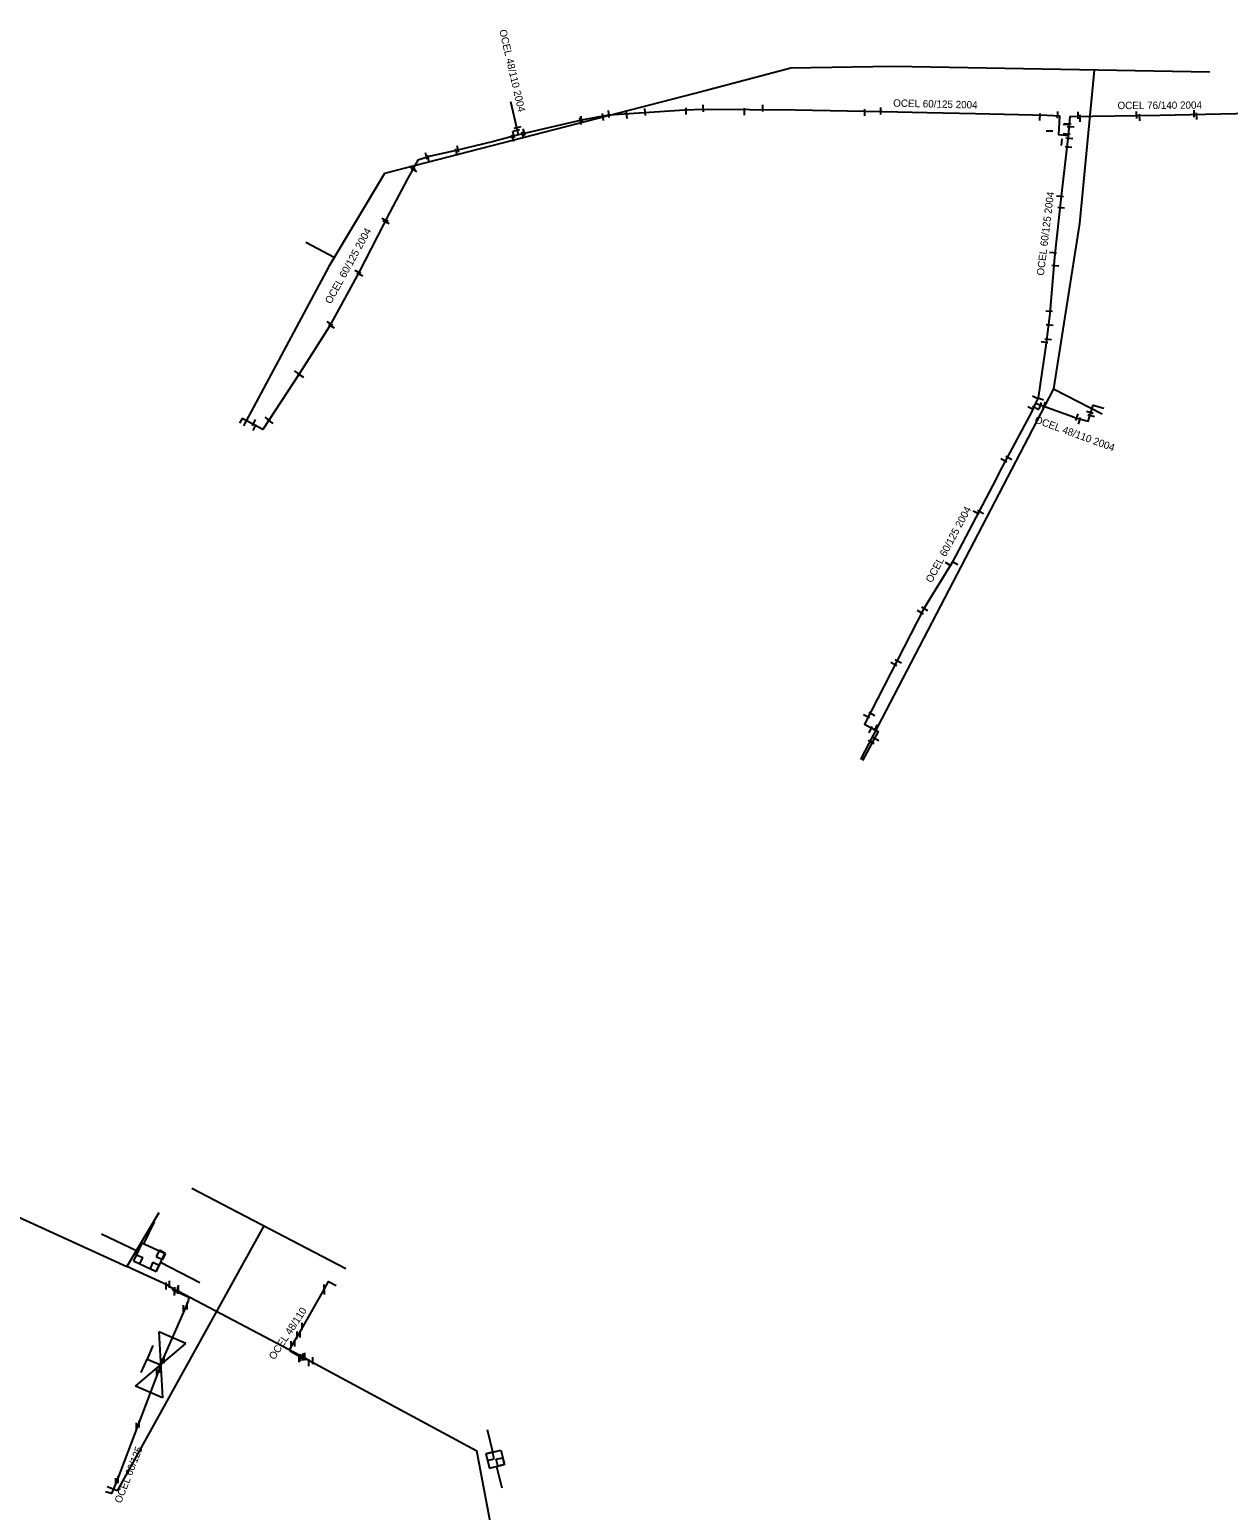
# Model space of a CAD drawing. Extents: x -642943 to -623314, y -1138561 to -1113539.
# Drawn here: x -642840.5 to -642718.5, y -1114329.8 to -1114179.2 of the extents above; entities that cross this region are included whole.
import ezdxf

# ---------------------------------------------------------------- set-up
doc = ezdxf.new("R2010")
doc.units = 0
for name, color, linetype in [('horkovod armatury', 7, 'Continuous'), ('horkovod dimenze', 7, 'Continuous'), ('horkovod předisol', 7, 'Continuous'), ('horkovod sváry', 7, 'Continuous'), ('horkovod trasa', 7, 'Continuous'), ('horkovod zrušený', 7, 'Continuous')]:
    doc.layers.add(name, color=color, linetype=linetype)

# ---------------------------------------------------------------- blocks, each defined once
blk = doc.blocks.new('POINT_DISPLAY')
blk.add_line((0, 0), (0, 0))
blk = doc.blocks.new('SPH')
at = {"layer": 'horkovod sváry'}
blk.add_line((0, -0.035), (0, 0.035), dxfattribs=at)
blk = doc.blocks.new('SCH_01_104')
at = {"layer": 'horkovod armatury'}
for p, q in [((10, 5), (-10, -5)), ((-10, -5), (-10, 5)), ((-10, 5), (10, -5)), ((-5, 5), (0, 5)), ((0, 5), (0, 0)), ((5, 5), (0, 5)), ((10, -5), (10, 5))]:
    blk.add_line(p, q, dxfattribs=at)

msp = doc.modelspace()

# ---------------------------------------------------------------- linework, layer by layer
at = {"layer": 'horkovod předisol'}
for p, q in [((-642790.76, -1114189.89), (-642791.55, -1114186.51)), ((-642827.34, -1114299.55), (-642830.61, -1114305.01)), ((-642812.3, -1114314.43), (-642825.98, -1114307.21)), ((-642812.3, -1114314.43), (-642795, -1114323.77)), ((-642788.02, -1114360.57), (-642795, -1114323.77))]:
    msp.add_line(p, q, dxfattribs=at)
for points in [[(-642734.85, -1114189.98), (-642735.8, -1114189.89), (-642735.7, -1114188), (-642736.98, -1114187.93), (-642744.26, -1114187.76), (-642749.19, -1114187.65), (-642753.72, -1114187.55), (-642762.62, -1114187.38), (-642771.87, -1114187.31), (-642773.86, -1114187.38), (-642781.54, -1114187.89), (-642781.97, -1114187.94), (-642784.36, -1114188.38), (-642790.76, -1114189.89)], [(-642714.7, -1114187.68), (-642725.5, -1114187.91), (-642734.68, -1114188.06), (-642734.85, -1114189.98)], [(-642790.76, -1114189.89), (-642793.31, -1114190.55), (-642797.1, -1114191.47), (-642799.72, -1114192.07), (-642800.99, -1114192.45), (-642802.06, -1114194.37), (-642803.84, -1114197.75), (-642806.99, -1114203.89), (-642810.02, -1114209.41), (-642813.03, -1114214.18), (-642816.75, -1114219.86), (-642818.86, -1114218.73), (-642819.14, -1114219.2)], [(-642734.85, -1114189.98), (-642735.54, -1114196.12), (-642736.24, -1114202.32), (-642736.7, -1114208.07), (-642737.11, -1114211.3), (-642737.91, -1114216.63), (-642738.15, -1114217.18)], [(-642738.15, -1114217.18), (-642738.54, -1114218.02), (-642741.79, -1114224.11), (-642742.17, -1114224.89), (-642746.65, -1114233.38), (-642749.56, -1114238.14), (-642755.55, -1114249.83), (-642754.16, -1114250.58), (-642755.76, -1114253.53)], [(-642738.15, -1114217.18), (-642734.41, -1114218.55), (-642733.99, -1114218.71), (-642732.82, -1114219), (-642732.31, -1114217.38), (-642731.21, -1114217.69)], [(-642877.13, -1114282.34), (-642874.67, -1114283.67), (-642863.97, -1114289.15), (-642853.5, -1114294.39), (-642852.54, -1114294.82), (-642851.65, -1114293.04), (-642849.52, -1114294.1), (-642850.35, -1114295.88), (-642849.53, -1114296.38), (-642830.61, -1114305.01)], [(-642825.98, -1114307.21), (-642826.45, -1114306.9), (-642830.61, -1114305.01)], [(-642812.3, -1114314.43), (-642812.45, -1114314.52), (-642813.96, -1114313.65), (-642813.99, -1114313.4), (-642813.7, -1114312.89), (-642812.96, -1114311.66), (-642810.51, -1114307.36), (-642810.07, -1114306.55), (-642809.29, -1114306.96)], [(-642825.98, -1114307.21), (-642825.91, -1114307.38), (-642824.29, -1114308.14), (-642824.35, -1114308.5), (-642824.64, -1114309.17), (-642826.96, -1114314.52), (-642827.42, -1114315.72), (-642829.49, -1114321.19), (-642831.62, -1114326.8), (-642832.14, -1114328.1), (-642832.78, -1114327.93)]]:
    msp.add_lwpolyline(points, dxfattribs=at)
at = {"layer": 'horkovod trasa'}
for p, q in [((-642790.76, -1114189.89), (-642791.55, -1114186.51)), ((-642827.34, -1114299.55), (-642830.61, -1114305.01)), ((-642812.3, -1114314.43), (-642825.98, -1114307.21)), ((-642812.3, -1114314.43), (-642795, -1114323.77)), ((-642788.02, -1114360.57), (-642795, -1114323.77))]:
    msp.add_line(p, q, dxfattribs=at)
for points in [[(-642734.85, -1114189.98), (-642735.8, -1114189.89), (-642735.7, -1114188), (-642736.98, -1114187.93), (-642744.26, -1114187.76), (-642749.19, -1114187.65), (-642753.72, -1114187.55), (-642762.62, -1114187.38), (-642771.87, -1114187.31), (-642773.86, -1114187.38), (-642781.54, -1114187.89), (-642781.97, -1114187.94), (-642784.36, -1114188.38), (-642790.76, -1114189.89)], [(-642714.7, -1114187.68), (-642725.5, -1114187.91), (-642734.68, -1114188.06), (-642734.85, -1114189.98)], [(-642790.76, -1114189.89), (-642793.31, -1114190.55), (-642797.1, -1114191.47), (-642799.72, -1114192.07), (-642800.99, -1114192.45), (-642802.06, -1114194.37), (-642803.84, -1114197.75), (-642806.99, -1114203.89), (-642810.02, -1114209.41), (-642813.03, -1114214.18), (-642816.75, -1114219.86), (-642818.86, -1114218.73), (-642819.14, -1114219.2)], [(-642734.85, -1114189.98), (-642735.54, -1114196.12), (-642736.24, -1114202.32), (-642736.7, -1114208.07), (-642737.11, -1114211.3), (-642737.91, -1114216.63), (-642738.15, -1114217.18)], [(-642738.15, -1114217.18), (-642738.54, -1114218.02), (-642741.79, -1114224.11), (-642742.17, -1114224.89), (-642746.65, -1114233.38), (-642749.56, -1114238.14), (-642755.55, -1114249.83), (-642754.16, -1114250.58), (-642755.76, -1114253.53)], [(-642738.15, -1114217.18), (-642734.41, -1114218.55), (-642733.99, -1114218.71), (-642732.82, -1114219), (-642732.31, -1114217.38), (-642731.21, -1114217.69)], [(-642877.13, -1114282.34), (-642874.67, -1114283.67), (-642863.97, -1114289.15), (-642853.5, -1114294.39), (-642852.54, -1114294.82), (-642851.65, -1114293.04), (-642849.52, -1114294.1), (-642850.35, -1114295.88), (-642849.53, -1114296.38), (-642830.61, -1114305.01)], [(-642825.98, -1114307.21), (-642826.45, -1114306.9), (-642830.61, -1114305.01)], [(-642812.3, -1114314.43), (-642812.45, -1114314.52), (-642813.96, -1114313.65), (-642813.99, -1114313.4), (-642813.7, -1114312.89), (-642812.96, -1114311.66), (-642810.51, -1114307.36), (-642810.07, -1114306.55), (-642809.29, -1114306.96)], [(-642825.98, -1114307.21), (-642825.91, -1114307.38), (-642824.29, -1114308.14), (-642824.35, -1114308.5), (-642824.64, -1114309.17), (-642826.96, -1114314.52), (-642827.42, -1114315.72), (-642829.49, -1114321.19), (-642831.62, -1114326.8), (-642832.14, -1114328.1), (-642832.78, -1114327.93)]]:
    msp.add_lwpolyline(points, dxfattribs=at)
at = {"layer": 'horkovod zrušený'}
for p, q in [((-642804.38, -1114193.8), (-642810.05, -1114203.28)), ((-642809.51, -1114202.37), (-642812.37, -1114200.83)), ((-642810.05, -1114203.28), (-642818.73, -1114219.5)), ((-642736.35, -1114215.71), (-642755.96, -1114253.43)), ((-642736.35, -1114215.71), (-642731.4, -1114218.27)), ((-642823.97, -1114297.05), (-642808.32, -1114305.22)), ((-642828.88, -1114302.72), (-642827.78, -1114300.47)), ((-642829.47, -1114303.5), (-642833.17, -1114301.71)), ((-642831.53, -1114327.84), (-642816.61, -1114300.89)), ((-642829.06, -1114302.63), (-642829.9, -1114304.45)), ((-642826.76, -1114303.7), (-642829.06, -1114302.63)), ((-642827.28, -1114303.36), (-642827.6, -1114303.98)), ((-642826.66, -1114303.68), (-642827.28, -1114303.36)), ((-642829.61, -1114303.81), (-642829.9, -1114304.45)), ((-642829.9, -1114304.45), (-642829.27, -1114304.74)), ((-642829.9, -1114304.45), (-642827.6, -1114305.51)), ((-642829.61, -1114303.81), (-642828.97, -1114304.11)), ((-642829.27, -1114304.74), (-642828.97, -1114304.11)), ((-642827.94, -1114304.58), (-642828.23, -1114305.22)), ((-642827.94, -1114304.58), (-642827.31, -1114304.88)), ((-642826.76, -1114303.7), (-642827.6, -1114305.51)), ((-642827.6, -1114303.98), (-642826.98, -1114304.3)), ((-642827.6, -1114305.51), (-642827.31, -1114304.88)), ((-642827.16, -1114304.57), (-642823.18, -1114306.65)), ((-642826.66, -1114303.68), (-642826.98, -1114304.3)), ((-642828.23, -1114305.22), (-642827.6, -1114305.51)), ((-642793.36, -1114323.88), (-642793.89, -1114321.64)), ((-642794.06, -1114324.06), (-642792.55, -1114323.68)), ((-642793.39, -1114323.89), (-642794.06, -1114324.06)), ((-642794.06, -1114324.06), (-642793.7, -1114325.51)), ((-642794.06, -1114324.06), (-642793.9, -1114324.74)), ((-642793.9, -1114324.74), (-642793.22, -1114324.57)), ((-642793.22, -1114324.57), (-642793.39, -1114323.89)), ((-642793.04, -1114324.62), (-642792.36, -1114324.46)), ((-642792.87, -1114325.3), (-642793.04, -1114324.62)), ((-642792.55, -1114323.68), (-642792.19, -1114325.14)), ((-642792.19, -1114325.13), (-642792.36, -1114324.46)), ((-642793.7, -1114325.51), (-642792.19, -1114325.14)), ((-642792.99, -1114325.34), (-642792.45, -1114327.52)), ((-642792.87, -1114325.3), (-642792.19, -1114325.13)), ((-642831.53, -1114327.84), (-642832.61, -1114327.44))]:
    msp.add_line(p, q, dxfattribs=at)
for points in [[(-642720.43, -1114183.5), (-642752.65, -1114182.92), (-642763.06, -1114183.11), (-642771.89, -1114185.45), (-642804.38, -1114193.8)], [(-642732.19, -1114183.29), (-642733.68, -1114198.91), (-642736.35, -1114215.71)]]:
    msp.add_lwpolyline(points, dxfattribs=at)

# ---------------------------------------------------------------- block references
at = {"layer": 'horkovod armatury', "xscale": 0.30001177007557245, "yscale": 0.30001177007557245, "rotation": 66.69397856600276}
msp.add_blockref('SCH_01_104', (-642827.15, -1114315.02), dxfattribs=at)
at = {"layer": 'horkovod sváry'}
for p, xscale, yscale, rotation in [((-642781.55, -1114187.77), 9.999987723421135, 9.999987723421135, 5.336341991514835), ((-642779.74, -1114187.88), 9.999983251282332, 9.999983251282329, 4.461219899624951), ((-642777.87, -1114187.56), 9.999997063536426, 9.999997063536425, 3.028577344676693), ((-642773.7, -1114187.47), 10.000000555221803, 10.000000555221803, -0.4949288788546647), ((-642771.95, -1114187.18), 10.000021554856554, 10.00002155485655, 0.8287225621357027), ((-642735.9, -1114187.85), 10.000004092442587, 10.000004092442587, -2.7264378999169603), ((-642727.87, -1114187.86), 9.999978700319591, 9.999978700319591, 1.5692780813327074), ((-642722.07, -1114187.74), 9.999989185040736, 9.999989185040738, -179.1656712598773), ((-642790.84, -1114189.12), 9.999981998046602, 9.9999819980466, -77.58877188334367), ((-642784.45, -1114188.51), 10.000013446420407, 10.00001344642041, 10.431419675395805), ((-642784.36, -1114188.29), 9.999989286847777, 9.999989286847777, -167.85582430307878), ((-642782.15, -1114188.07), 10.000008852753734, 10.000008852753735, 7.349255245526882), ((-642737.7, -1114188.07), 9.999987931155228, 9.999987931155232, -1.7724017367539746), ((-642735, -1114188.81), 9.999956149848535, 9.999956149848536, -91.98650099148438), ((-642734.89, -1114188.79), 10.00000465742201, 10.00000465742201, 87.73957876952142), ((-642734.59, -1114189.09), 10.000013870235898, 10.000013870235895, 86.28481462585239), ((-642727.56, -1114188.12), 10.000013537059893, 10.000013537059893, 1.8196447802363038), ((-642721.8, -1114187.98), 9.99998740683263, 9.999987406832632, -178.70641920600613), ((-642791.32, -1114190.21), 9.999986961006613, 9.999986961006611, 15.945469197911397), ((-642791.25, -1114189.89), 10.000000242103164, 10.000000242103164, 15.068547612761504), ((-642790.96, -1114189.43), 10.000004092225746, 10.000004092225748, -77.14776805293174), ((-642790.34, -1114189.93), 9.999986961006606, 9.99998696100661, -164.0545308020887), ((-642790.21, -1114189.61), 10.000000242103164, 10.000000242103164, -164.9314523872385), ((-642736.74, -1114189.52), 10.000009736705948, 10.000009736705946, 89.10483462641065), ((-642735.51, -1114190.63), 10.000012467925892, 10.00001246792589, 174.39082038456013), ((-642734.99, -1114189.79), 10.000005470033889, 10.00000547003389, -95.96853483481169), ((-642734.72, -1114190.21), 10.000022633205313, 10.000022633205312, -96.31119957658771), ((-642800.13, -1114192.04), 10.00001789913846, 10.000017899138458, 12.889708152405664), ((-642799.93, -1114192.3), 9.999984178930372, 9.99998417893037, 13.274328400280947), ((-642797.09, -1114191.63), 9.999984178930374, 9.999984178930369, -166.72567159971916), ((-642796.94, -1114191.31), 10.00001789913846, 10.000017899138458, -167.11029184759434), ((-642734.81, -1114191.11), 9.999996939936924, 9.999996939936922, -96.90130667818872), ((-642801.54, -1114193.24), 9.999980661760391, 9.999980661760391, -117.85237207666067), ((-642801.41, -1114193.44), 9.999977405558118, 9.99997740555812, -118.01636364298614), ((-642735.68, -1114196.16), 10.000014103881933, 10.00001410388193, 83.73308427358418), ((-642735.56, -1114197.31), 9.999981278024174, 9.99998127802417, 82.95003885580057), ((-642804.33, -1114198.52), 10.00002106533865, 10.00002106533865, -117.4642718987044), ((-642804.23, -1114198.74), 10.000020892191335, 10.000020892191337, -116.39442554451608), ((-642736.39, -1114201.89), 9.99999810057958, 9.999998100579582, 83.99095214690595), ((-642807.09, -1114203.83), 10.00002106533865, 10.00002106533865, 62.535728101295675), ((-642806.9, -1114204.12), 10.000020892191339, 10.000020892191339, 63.60557445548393), ((-642736.14, -1114203.21), 9.999980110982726, 9.999980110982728, 84.35460904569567), ((-642736.78, -1114207.85), 9.999979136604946, 9.999979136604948, 86.27143324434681), ((-642809.96, -1114209.05), 9.99999504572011, 9.999995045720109, -123.0037904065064), ((-642809.79, -1114209.35), 10.000001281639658, 10.00000128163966, -121.76493540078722), ((-642736.72, -1114209.25), 10.000000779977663, 10.000000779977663, 84.70894959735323), ((-642737.24, -1114210.96), 9.999998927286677, 9.999998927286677, -98.47497390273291), ((-642736.87, -1114210.67), 10.000010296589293, 10.00001029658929, -98.16191030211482), ((-642813.24, -1114214.1), 10.000016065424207, 10.000016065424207, 54.65191950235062), ((-642812.9, -1114214.39), 9.999998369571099, 9.999998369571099, 58.322879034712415), ((-642738.64, -1114217.71), 10.000021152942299, 10.000021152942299, 63.39092031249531), ((-642738.17, -1114216.62), 10.000021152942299, 10.000021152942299, 63.39092031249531), ((-642738.15, -1114217.69), 10.000021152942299, 10.000021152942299, 63.39092031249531), ((-642737.67, -1114216.72), 10.00000690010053, 10.000006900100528, -111.88290998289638), ((-642737.68, -1114217.46), 9.99999636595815, 9.999996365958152, -19.583991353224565), ((-642737.26, -1114217.39), 10.000021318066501, 10.000021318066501, -19.819440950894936), ((-642817.67, -1114219.16), 10.000013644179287, 10.000013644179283, -25.187505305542), ((-642816.25, -1114218.8), 10.000016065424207, 10.000016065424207, 54.65191950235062), ((-642815.99, -1114219.04), 10.000016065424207, 10.000016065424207, 54.65191950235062), ((-642733.95, -1114218.6), 10.000002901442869, 10.000002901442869, -18.43486445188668), ((-642733.68, -1114218.97), 9.99999124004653, 9.999991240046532, -17.402696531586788), ((-642732.65, -1114218.11), 10.000009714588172, 10.000009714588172, -106.91651534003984), ((-642732.51, -1114218.43), 10.000003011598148, 10.000003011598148, -108.23811081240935), ((-642817.59, -1114219.66), 10.000013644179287, 10.000013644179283, -25.187505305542), ((-642741.38, -1114223.01), 10.000007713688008, 10.000007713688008, 59.07046940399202), ((-642740.88, -1114222.79), 9.999997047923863, 9.99999704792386, 61.250409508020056), ((-642744.2, -1114228.32), 9.999995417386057, 9.999995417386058, 61.55701272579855), ((-642743.77, -1114228.27), 9.999989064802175, 9.999989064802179, 60.542864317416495), ((-642747.01, -1114233.58), 10.000030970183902, 10.000030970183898, 60.00811216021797), ((-642746.38, -1114233.47), 10.00000433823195, 10.00000433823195, 61.62589691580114), ((-642749.86, -1114238.47), 9.999976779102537, 9.999976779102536, 59.079071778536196), ((-642749.42, -1114238.12), 9.99997231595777, 9.999972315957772, 56.709009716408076), ((-642752.12, -1114243.46), 10.000002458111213, 10.000002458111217, 61.801016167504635), ((-642752.57, -1114243.74), 9.999993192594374, 9.999993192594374, 62.92795671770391), ((-642755.35, -1114249.04), 10.000041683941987, 10.000041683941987, 61.25937461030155), ((-642754.81, -1114248.82), 10.000032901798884, 10.000032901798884, 59.187743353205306), ((-642754.93, -1114250.4), 10.000007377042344, 10.000007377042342, -25.670841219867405), ((-642754.38, -1114250.19), 10.000007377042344, 10.000007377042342, -25.670841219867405), ((-642754.89, -1114251.66), 10.000036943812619, 10.000036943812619, 62.471408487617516), ((-642754.42, -1114251.36), 9.999993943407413, 9.99999394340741, 60.69780913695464)]:
    msp.add_blockref('SPH', p, dxfattribs=dict(at, xscale=xscale, yscale=yscale, rotation=rotation))
at = {"layer": 'horkovod sváry', "xscale": 10, "yscale": 10}
for p in [(-642767.75, -1114187.52), (-642765.89, -1114187.17), (-642755.52, -1114187.61), (-642753.9, -1114187.46), (-642733.81, -1114187.89), (-642733.62, -1114188.21), (-642826.27, -1114306.83), (-642826.59, -1114306.99), (-642825.73, -1114307.6), (-642825.7, -1114307.47), (-642825.39, -1114307.44), (-642825.34, -1114307.27), (-642810.52, -1114307.18), (-642810.5, -1114307.52), (-642824.82, -1114309.28), (-642824.46, -1114309.03), (-642812.75, -1114311.08), (-642813.87, -1114312.96), (-642813.51, -1114312.79), (-642813.27, -1114311.97), (-642812.97, -1114311.89), (-642826.8, -1114314.48), (-642813.05, -1114314.4), (-642812.91, -1114314.29), (-642812.67, -1114314.22), (-642812.5, -1114314.13), (-642827.54, -1114315.64), (-642827.17, -1114315.48), (-642827.15, -1114314.67), (-642812.07, -1114314.79), (-642811.69, -1114314.59), (-642829.61, -1114321.27), (-642829.34, -1114321.05), (-642831.72, -1114326.88), (-642831.46, -1114326.7)]:
    msp.add_blockref('SPH', p, dxfattribs=at)
at = {"layer": 'horkovod zrušený'}
for p in [(-642829.44, -1114304.28), (-642827.77, -1114305.05), (-642827.13, -1114303.83), (-642793.64, -1114324.31), (-642792.61, -1114324.88)]:
    msp.add_blockref('POINT_DISPLAY', p, dxfattribs=at)

# ---------------------------------------------------------------- texts
at = {"layer": 'horkovod dimenze'}
for s, rotation, p in [('OCEL 48/110 2004', 283.1527, (-642792.72, -1114179.26)), ('OCEL 60/125 2004', 358.6145, (-642752.65, -1114187.01)), ('OCEL 76/140 2004', 0.2894, (-642729.82, -1114187.27)), ('OCEL 60/125 2004', 82.9365, (-642737.32, -1114204.24)), ('OCEL 60/125 2004', 61.1976, (-642809.83, -1114207.15)), ('OCEL 48/110 2004', 339.9197, (-642738.33, -1114219.15)), ('OCEL 60/125 2004', 61.888, (-642748.72, -1114235.52)), ('OCEL 48/110', 56.7393, (-642815.58, -1114314.56)), ('OCEL 60/125', 68.7097, (-642831.18, -1114329.16))]:
    msp.add_text(s, height=0.75, rotation=rotation, dxfattribs=at).set_placement(p)

doc.saveas('drawing.dxf')
